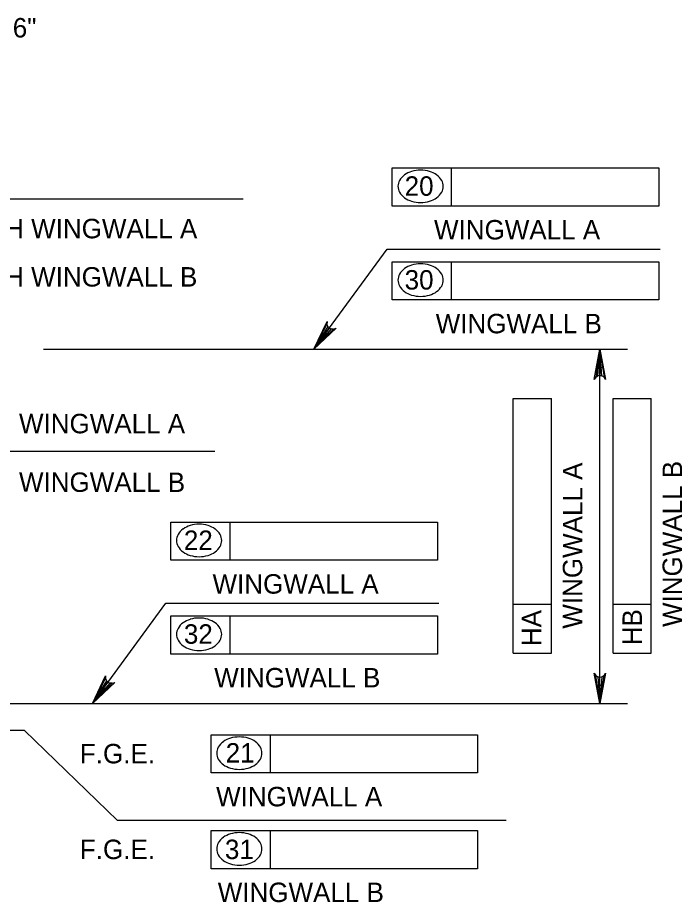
# Model space of a CAD drawing. Extents: x 638304 to 640306, y 296653 to 298435.
# Drawn here: x 638939.9 to 639042.4, y 297962.8 to 298099.3 of the extents above; entities that cross this region are included whole.
import ezdxf

# ---------------------------------------------------------------- set-up
doc = ezdxf.new("R2010")
doc.units = 0
doc.layers.add('Level 5', color=7, linetype='Continuous')

msp = doc.modelspace()

# ---------------------------------------------------------------- linework, layer by layer
at = {"layer": 'Level 5'}
for p, q in [((638997.69, 298070.24), (638997.69, 298076.14)), ((638997.69, 298076.14), (639038.82, 298076.14)), ((639006.85, 298070.24), (639006.85, 298076.14)), ((639038.82, 298076.14), (639038.82, 298070.24)), ((638881.18, 298071.38), (638974.68, 298071.38)), ((639038.82, 298070.24), (638997.69, 298070.24)), ((638997.69, 298061.67), (639038.82, 298061.67)), ((638997.69, 298055.77), (638997.69, 298061.67)), ((639006.85, 298055.77), (639006.85, 298061.67)), ((639038.82, 298061.67), (639038.82, 298055.77)), ((639038.82, 298055.77), (638997.69, 298055.77)), ((638943.86, 298048.16), (639033.98, 298048.16)), ((639029.73, 297993.51), (639029.73, 298048.16)), ((639016.35, 298001.28), (639016.35, 298040.58)), ((639016.35, 298040.58), (639022.25, 298040.58)), ((639022.25, 298001.28), (639022.25, 298040.58)), ((639031.75, 298040.58), (639037.64, 298040.58)), ((639031.75, 298001.28), (639031.75, 298040.58)), ((639037.64, 298001.28), (639037.64, 298040.58)), ((638970.34, 298032.4), (638895.65, 298032.4)), ((638963.52, 298021.49), (639004.65, 298021.49)), ((638963.52, 298015.6), (638963.52, 298021.49)), ((638972.67, 298015.6), (638972.67, 298021.49)), ((639004.65, 298021.49), (639004.65, 298015.6)), ((639004.65, 298015.6), (638963.52, 298015.6)), ((639016.35, 298008.83), (639022.25, 298008.83)), ((639031.75, 298008.83), (639037.64, 298008.83)), ((638963.52, 298007.02), (639004.65, 298007.02)), ((638963.52, 298001.13), (638963.52, 298007.02)), ((638972.67, 298001.13), (638972.67, 298007.02)), ((639004.65, 298007.02), (639004.65, 298001.13)), ((639004.65, 298001.13), (638963.52, 298001.13)), ((639016.35, 298001.28), (639022.25, 298001.28)), ((639031.75, 298001.28), (639037.64, 298001.28)), ((638932.72, 297993.51), (639033.98, 297993.51)), ((638940.93, 297989.33), (638932.66, 297989.33)), ((638940.93, 297989.33), (638955.32, 297975.46)), ((638969.73, 297988.67), (639010.86, 297988.67)), ((638969.73, 297982.78), (638969.73, 297988.67)), ((638978.88, 297982.78), (638978.88, 297988.67)), ((639010.86, 297988.67), (639010.86, 297982.78)), ((639010.86, 297982.78), (638969.73, 297982.78)), ((639015.28, 297975.46), (638955.32, 297975.46)), ((638969.73, 297973.9), (639010.86, 297973.9)), ((638969.73, 297968.01), (638969.73, 297973.9)), ((638978.88, 297968.01), (638978.88, 297973.9)), ((639010.86, 297973.9), (639010.86, 297968.01)), ((639010.86, 297968.01), (638969.73, 297968.01))]:
    msp.add_line(p, q, dxfattribs=at)
for points in [[(638985.59, 298048.16), (638996.91, 298063.62), (639039.02, 298063.62)], [(638985.59, 298048.16), (638987.63, 298052.43), (638987.62, 298051.99), (638987.77, 298051.66), (638987.99, 298051.43), (638988.27, 298051.29), (638988.63, 298051.25), (638989.04, 298051.4), (638985.59, 298048.16), (638988.63, 298051.25), (638988.27, 298051.29), (638985.59, 298048.16), (638987.99, 298051.43), (638987.77, 298051.66), (638985.59, 298048.16), (638987.62, 298051.99)], [(639029.73, 298048.16), (639030.6, 298043.51), (639030.36, 298043.86), (639030.04, 298044.05), (639029.73, 298044.1), (639029.42, 298044.05), (639029.11, 298043.86), (639028.86, 298043.51), (639029.73, 298048.16), (639029.11, 298043.86), (639029.42, 298044.05), (639029.73, 298048.16), (639029.73, 298044.1), (639030.04, 298044.05), (639029.73, 298048.16), (639030.36, 298043.86)], [(638951.42, 297993.51), (638962.74, 298008.97), (639004.85, 298008.97)], [(639029.73, 297993.51), (639028.86, 297998.17), (639029.11, 297997.81), (639029.42, 297997.62), (639029.73, 297997.57), (639030.04, 297997.62), (639030.36, 297997.81), (639030.6, 297998.17), (639029.73, 297993.51), (639030.36, 297997.81), (639030.04, 297997.62), (639029.73, 297993.51), (639029.73, 297997.57), (639029.42, 297997.62), (639029.73, 297993.51), (639029.11, 297997.81)], [(638951.42, 297993.51), (638953.46, 297997.78), (638953.45, 297997.35), (638953.59, 297997.01), (638953.81, 297996.79), (638954.1, 297996.65), (638954.46, 297996.61), (638954.87, 297996.75), (638951.42, 297993.51), (638954.46, 297996.61), (638954.1, 297996.65), (638951.42, 297993.51), (638953.81, 297996.79), (638953.59, 297997.01), (638951.42, 297993.51), (638953.45, 297997.35)]]:
    msp.add_lwpolyline(points, dxfattribs=at)
for points in [[(638985.59, 298048.16), (638987.53, 298050.39), (638987.13, 298050.68)], [(639029.26, 298045.33), (639030.2, 298045.33), (639029.73, 298048.16)], [(638951.42, 297993.51), (638953.36, 297995.75), (638952.96, 297996.04)], [(639029.26, 297996.34), (639030.2, 297996.34), (639029.73, 297993.51)]]:
    msp.add_lwpolyline(points, close=True, dxfattribs=at)
for centre, radius, start, end in [((639002.06, 298070.94), 4.86, 90, 106.5358), ((639002.06, 298070.94), 4.86, 73.4642, 90), ((639001.19, 298072.83), 2.75, 125.6316, 149.9767), ((639001.72, 298072.1), 3.65, 106.5358, 125.6316), ((639002.41, 298072.1), 3.65, 54.3684, 73.4642), ((639002.93, 298072.83), 2.75, 30.0233, 54.3684), ((639000.39, 298073.3), 1.82, 149.9767, 180), ((639000.39, 298073.3), 1.82, 180, 210.0233), ((639003.74, 298073.3), 1.82, 0, 30.0233), ((639003.74, 298073.3), 1.82, 329.9767, 0), ((639001.19, 298073.76), 2.75, 210.0233, 234.3684), ((639002.93, 298073.76), 2.75, 305.6316, 329.9767), ((639001.72, 298074.49), 3.65, 234.3684, 253.4642), ((639002.06, 298075.65), 4.86, 253.4642, 270), ((639002.06, 298075.65), 4.86, 270, 286.5358), ((639002.41, 298074.49), 3.65, 286.5358, 305.6316), ((639001.72, 298057.63), 3.65, 106.5358, 125.6316), ((639002.06, 298056.47), 4.86, 90, 106.5358), ((639002.06, 298056.47), 4.86, 73.4642, 90), ((639002.41, 298057.63), 3.65, 54.3684, 73.4642), ((639000.39, 298058.83), 1.82, 149.9767, 180), ((639001.19, 298058.36), 2.75, 125.6316, 149.9767), ((639002.93, 298058.36), 2.75, 30.0233, 54.3684), ((639003.74, 298058.83), 1.82, 0, 30.0233), ((639000.39, 298058.83), 1.82, 180, 210.0233), ((639003.74, 298058.83), 1.82, 329.9767, 0), ((639001.19, 298059.29), 2.75, 210.0233, 234.3684), ((639001.72, 298060.02), 3.65, 234.3684, 253.4642), ((639002.41, 298060.02), 3.65, 286.5358, 305.6316), ((639002.93, 298059.29), 2.75, 305.6316, 329.9767), ((639002.06, 298061.18), 4.86, 253.4642, 270), ((639002.06, 298061.18), 4.86, 270, 286.5358), ((638967.02, 298018.19), 2.75, 125.6316, 149.9767), ((638967.55, 298017.45), 3.65, 106.5358, 125.6316), ((638967.89, 298016.3), 4.86, 90, 106.5358), ((638967.89, 298016.3), 4.86, 73.4642, 90), ((638968.23, 298017.45), 3.65, 54.3684, 73.4642), ((638968.76, 298018.19), 2.75, 30.0233, 54.3684), ((638966.22, 298018.65), 1.82, 149.9767, 180), ((638966.22, 298018.65), 1.82, 180, 210.0233), ((638969.56, 298018.65), 1.82, 0, 30.0233), ((638969.56, 298018.65), 1.82, 329.9767, 0), ((638967.02, 298019.12), 2.75, 210.0233, 234.3684), ((638968.76, 298019.12), 2.75, 305.6316, 329.9767), ((638967.55, 298019.85), 3.65, 234.3684, 253.4642), ((638967.89, 298021.01), 4.86, 253.4642, 270), ((638967.89, 298021.01), 4.86, 270, 286.5358), ((638968.23, 298019.85), 3.65, 286.5358, 305.6316), ((638967.55, 298002.98), 3.65, 106.5358, 125.6316), ((638967.89, 298001.83), 4.86, 90, 106.5358), ((638967.89, 298001.83), 4.86, 73.4642, 90), ((638968.23, 298002.98), 3.65, 54.3684, 73.4642), ((638966.22, 298004.18), 1.82, 149.9767, 180), ((638967.02, 298003.72), 2.75, 125.6316, 149.9767), ((638968.76, 298003.72), 2.75, 30.0233, 54.3684), ((638969.56, 298004.18), 1.82, 0, 30.0233), ((638966.22, 298004.18), 1.82, 180, 210.0233), ((638969.56, 298004.18), 1.82, 329.9767, 0), ((638967.02, 298004.65), 2.75, 210.0233, 234.3684), ((638967.55, 298005.38), 3.65, 234.3684, 253.4642), ((638968.23, 298005.38), 3.65, 286.5358, 305.6316), ((638968.76, 298004.65), 2.75, 305.6316, 329.9767), ((638967.89, 298006.54), 4.86, 253.4642, 270), ((638967.89, 298006.54), 4.86, 270, 286.5358), ((638973.23, 297985.37), 2.75, 125.6316, 149.9767), ((638973.75, 297984.64), 3.65, 106.5358, 125.6316), ((638974.1, 297983.48), 4.86, 90, 106.5358), ((638974.1, 297983.48), 4.86, 73.4642, 90), ((638974.44, 297984.64), 3.65, 54.3684, 73.4642), ((638974.97, 297985.37), 2.75, 30.0233, 54.3684), ((638972.42, 297985.83), 1.82, 149.9767, 180), ((638972.42, 297985.83), 1.82, 180, 210.0233), ((638975.77, 297985.83), 1.82, 0, 30.0233), ((638975.77, 297985.83), 1.82, 329.9767, 0), ((638973.23, 297986.3), 2.75, 210.0233, 234.3684), ((638974.97, 297986.3), 2.75, 305.6316, 329.9767), ((638973.75, 297987.03), 3.65, 234.3684, 253.4642), ((638974.1, 297988.19), 4.86, 253.4642, 270), ((638974.1, 297988.19), 4.86, 270, 286.5358), ((638974.44, 297987.03), 3.65, 286.5358, 305.6316), ((638974.1, 297968.71), 4.86, 90, 106.5358), ((638974.1, 297968.71), 4.86, 73.4642, 90), ((638973.23, 297970.6), 2.75, 125.6316, 149.9767), ((638973.75, 297969.87), 3.65, 106.5358, 125.6316), ((638974.44, 297969.87), 3.65, 54.3684, 73.4642), ((638974.97, 297970.6), 2.75, 30.0233, 54.3684), ((638972.42, 297971.06), 1.82, 149.9767, 180), ((638972.42, 297971.06), 1.82, 180, 210.0233), ((638975.77, 297971.06), 1.82, 0, 30.0233), ((638975.77, 297971.06), 1.82, 329.9767, 0), ((638973.23, 297971.53), 2.75, 210.0233, 234.3684), ((638974.97, 297971.53), 2.75, 305.6316, 329.9767), ((638973.75, 297972.26), 3.65, 234.3684, 253.4642), ((638974.1, 297973.42), 4.86, 253.4642, 270), ((638974.1, 297973.42), 4.86, 270, 286.5358), ((638974.44, 297972.26), 3.65, 286.5358, 305.6316)]:
    msp.add_arc(centre, radius, start, end, dxfattribs=at)

# ---------------------------------------------------------------- texts
for s, height, p in [('6"', 3, (638939.14, 298096.27)), ('20', 3, (638999.6, 298071.84)), ('LENGTH WINGWALL A', 3.0001, (638924.59, 298065.28)), ('WINGWALL A', 3, (639004.13, 298065.1)), ('LENGTH WINGWALL B', 3.0001, (638924.59, 298057.83)), ('30', 3, (638999.6, 298057.37)), ('WINGWALL B', 3, (639004.39, 298050.62)), ('22', 3, (638965.54, 298017.19)), ('WINGWALL A', 3, (638969.96, 298010.45)), ('32', 3, (638965.54, 298002.72)), ('WINGWALL B', 3, (638970.22, 297995.98)), ('F.G.E.', 3, (638949.5, 297984.26)), ('21', 3, (638971.99, 297984.38)), ('WINGWALL A', 3, (638970.51, 297977.63)), ('F.G.E.', 3, (638949.5, 297969.49)), ('31', 3, (638971.87, 297969.49)), ('WINGWALL B', 3, (638970.77, 297962.86))]:
    msp.add_text(s, height=height, dxfattribs=at).set_placement(p)
for s, rotation, p in [('WINGWALL A', 359.9382, (638940.1, 298035.2)), ('WINGWALL B', 89.9382, (639042.38, 298005.3)), ('WINGWALL A', 89.9382, (639026.99, 298005.04)), ('WINGWALL B', 359.9382, (638940.1, 298026.16)), ('HA', 89.9382, (639020.67, 298002.35)), ('HB', 89.9382, (639036.2, 298002.48))]:
    msp.add_text(s, height=3, rotation=rotation, dxfattribs=at).set_placement(p)

doc.saveas('drawing.dxf')
